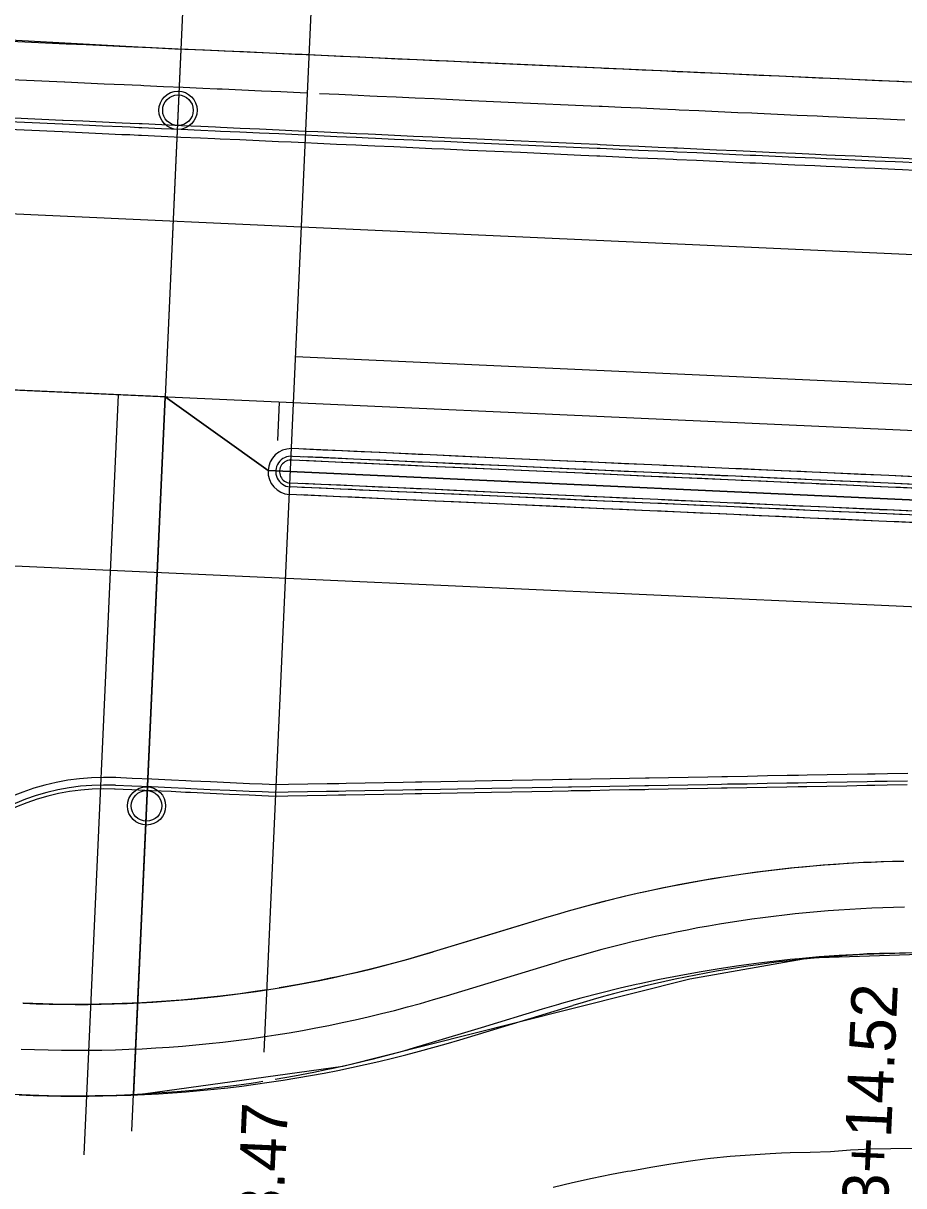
# Model space of a CAD drawing. Extents: x -70 to 701944, y -4 to 666871.
# Drawn here: x 665760.5 to 665875.7, y 656544.4 to 656696.4 of the extents above; entities that cross this region are included whole.
import ezdxf

# ---------------------------------------------------------------- set-up
doc = ezdxf.new("R2010")
doc.units = 0
for name, color, linetype in [('R_Detour', 7, 'Continuous'), ('R_Draft', 7, 'Continuous'), ('R_Horz Alg', 7, 'Continuous'), ('R_No Plot', 7, 'Continuous'), ('R_Proposed Const Limits', 7, 'Continuous'), ('R_Proposed Road', 7, 'Continuous'), ('R_Striping', 7, 'Continuous'), ('R_Water', 7, 'Continuous')]:
    doc.layers.add(name, color=color, linetype=linetype)

msp = doc.modelspace()

# ---------------------------------------------------------------- linework, layer by layer
at = {"layer": 'R_Detour'}
for p in [(665784.2, 656761.27), (665774.73, 656551.56)]:
    msp.add_line(p, (665779.07, 656647.56), dxfattribs=at)
at = {"layer": 'R_Draft'}
for p, q in [((665792.03, 656561.91), (665801.53, 656772.27)), ((665772.93, 656647.83), (665768.44, 656548.49))]:
    msp.add_line(p, q, dxfattribs=at)
at = {"layer": 'R_Horz Alg'}
msp.add_line((667725.26, 656559.62), (664961.47, 656684.5), dxfattribs=at)
msp.add_lwpolyline([(665793.82, 656641.88), (665794.05, 656646.88)], dxfattribs=at)
at = {"layer": 'R_No Plot'}
for p, q in [((667813.84, 656555.62), (664810.54, 656691.32)), ((667725.26, 656559.62), (664961.47, 656684.5)), ((665815.86, 656569.27), (665830.67, 656573.76))]:
    msp.add_line(p, q, dxfattribs=at)
for points in [[(665704.14, 656650.94), (665706.41, 656701.05), (665711.71, 656696.82), (665781.12, 656693.02), (665779.07, 656647.56)], [(665896, 656687.82), (665781.12, 656693.02), (665779.07, 656647.56), (665792.54, 656637.94), (665893.54, 656633.33)], [(665779.07, 656647.56), (665694.15, 656651.39), (665690.05, 656560.57), (665709.98, 656558.58), (665748.15, 656556.85), (665765.88, 656556.16), (665774.94, 656556.35)], [(665779.07, 656647.56), (665774.94, 656556.3), (665802.33, 656560.07), (665825, 656565.77), (665847.68, 656571.48), (665863.28, 656574.24), (665890.91, 656575.15), (665893.57, 656633.33), (665792.54, 656637.94)]]:
    msp.add_lwpolyline(points, close=True, dxfattribs=at)
for centre in [(665780.76, 656685.03), (665776.65, 656594.1)]:
    msp.add_circle(centre, 2.5, dxfattribs=at)
for centre, start, end in [((665878.78, 656414.88), 91.0369, 106.8465), ((665767.75, 656728.15), 267.4131, 286.8465)]:
    msp.add_arc(centre, 166, start, end, dxfattribs=at)
at = {"layer": 'R_Proposed Const Limits'}
msp.add_lwpolyline([(665879.73, 656549.3), (665873.97, 656549.29), (665871.34, 656549.21), (665869.72, 656549.13), (665868.7, 656549.08), (665866.07, 656548.9), (665863.44, 656548.81), (665860.82, 656548.74), (665859.69, 656548.7), (665858.21, 656548.62), (665855.59, 656548.46), (665852.99, 656548.26), (665850.38, 656547.99), (665849.64, 656547.9), (665847.79, 656547.65), (665845.2, 656547.26), (665842.61, 656546.83), (665840.04, 656546.37), (665839.56, 656546.29), (665837.47, 656545.9), (665834.92, 656545.38), (665832.37, 656544.82), (665829.84, 656544.21)], dxfattribs=at)
at = {"layer": 'R_Proposed Road'}
for p, q in [((665828.93, 656579.5), (665814.12, 656575.01)), ((665828.93, 656579.5), (665814.12, 656575.01)), ((665817.6, 656563.53), (665832.41, 656568.01))]:
    msp.add_line(p, q, dxfattribs=at)
for points in [[(665797.91, 656692.26), (665796.98, 656692.3), (665796.1, 656692.34), (665794.44, 656692.42), (665791.9, 656692.53), (665789.35, 656692.65), (665786.79, 656692.76), (665786.11, 656692.79), (665784.23, 656692.88), (665781.66, 656692.99), (665779.09, 656693.11), (665776.51, 656693.23), (665776.12, 656693.24), (665774.98, 656693.3), (665773.93, 656693.34), (665771.35, 656693.46), (665768.77, 656693.58), (665766.19, 656693.69), (665766.13, 656693.69), (665756.14, 656694.15)], [(665876.02, 656688.72), (665875.01, 656688.77), (665872.39, 656688.88), (665869.77, 656689), (665867.16, 656689.12), (665866.03, 656689.17), (665864.56, 656689.24), (665861.96, 656689.36), (665859.37, 656689.47), (665856.78, 656689.59), (665856.04, 656689.62), (665854.21, 656689.71), (665851.64, 656689.82), (665849.08, 656689.94), (665846.53, 656690.05), (665846.05, 656690.07), (665843.99, 656690.17), (665841.46, 656690.28), (665838.95, 656690.39), (665836.45, 656690.51), (665836.06, 656690.53), (665833.95, 656690.62), (665826.07, 656690.98), (665819.37, 656691.28), (665816.93, 656691.39), (665816.08, 656691.43), (665814.48, 656691.5), (665812.01, 656691.61), (665809.53, 656691.72), (665807.04, 656691.84), (665806.09, 656691.88), (665804.54, 656691.95), (665802.03, 656692.06), (665799.51, 656692.18), (665797.91, 656692.26)], [(665797.69, 656687.26), (665796.75, 656687.31), (665795.88, 656687.35), (665794.22, 656687.42), (665791.67, 656687.54), (665789.12, 656687.65), (665786.56, 656687.77), (665785.89, 656687.8), (665784, 656687.88), (665781.43, 656688), (665778.86, 656688.11), (665776.29, 656688.23), (665775.9, 656688.25), (665774.75, 656688.3), (665773.71, 656688.35), (665771.13, 656688.46), (665768.55, 656688.58), (665765.97, 656688.7), (665765.91, 656688.7), (665755.92, 656689.15)], [(665875.8, 656683.72), (665874.79, 656683.77), (665872.16, 656683.89), (665869.55, 656684.01), (665866.94, 656684.13), (665865.81, 656684.18), (665864.33, 656684.24), (665861.73, 656684.36), (665859.14, 656684.48), (665856.56, 656684.59), (665855.82, 656684.63), (665853.98, 656684.71), (665851.41, 656684.83), (665848.85, 656684.94), (665846.3, 656685.06), (665845.83, 656685.08), (665843.77, 656685.17), (665841.24, 656685.29), (665838.72, 656685.4), (665836.22, 656685.51), (665835.84, 656685.53), (665833.73, 656685.63), (665825.85, 656685.98), (665819.15, 656686.28), (665816.7, 656686.39), (665815.86, 656686.43), (665814.25, 656686.51), (665811.78, 656686.62), (665809.3, 656686.73), (665806.81, 656686.84), (665805.87, 656686.88), (665804.31, 656686.95), (665801.8, 656687.07), (665799.28, 656687.18)], [(665797.44, 656681.77), (665796.5, 656681.81), (665795.63, 656681.85), (665793.97, 656681.93), (665791.42, 656682.04), (665788.87, 656682.16), (665786.31, 656682.27), (665785.64, 656682.3), (665783.75, 656682.39), (665781.18, 656682.5), (665778.61, 656682.62), (665776.04, 656682.74), (665775.65, 656682.75), (665774.5, 656682.81), (665773.46, 656682.85), (665770.88, 656682.97), (665768.3, 656683.09), (665765.72, 656683.2), (665765.66, 656683.21), (665755.67, 656683.66)], [(665797.46, 656682.27), (665796.53, 656682.31), (665795.65, 656682.35), (665793.99, 656682.43), (665791.44, 656682.54), (665788.89, 656682.66), (665786.34, 656682.77), (665785.66, 656682.8), (665783.77, 656682.89), (665781.21, 656683), (665778.64, 656683.12), (665776.06, 656683.24), (665775.67, 656683.25), (665774.52, 656683.31), (665773.48, 656683.35), (665770.9, 656683.47), (665768.32, 656683.59), (665765.74, 656683.7), (665765.68, 656683.7), (665755.69, 656684.16)], [(665797.39, 656680.76), (665796.46, 656680.8), (665795.58, 656680.84), (665793.92, 656680.92), (665791.38, 656681.03), (665788.83, 656681.15), (665786.27, 656681.26), (665785.59, 656681.29), (665783.71, 656681.38), (665781.14, 656681.49), (665778.57, 656681.61), (665775.99, 656681.73), (665775.6, 656681.74), (665774.46, 656681.8), (665773.41, 656681.84), (665770.84, 656681.96), (665768.25, 656682.08), (665765.67, 656682.19), (665765.62, 656682.2), (665755.63, 656682.65)], [(665877.18, 656678.66), (665875.57, 656678.73), (665874.56, 656678.78), (665871.94, 656678.89), (665869.32, 656679.01), (665866.71, 656679.13), (665865.58, 656679.18), (665864.11, 656679.25), (665861.51, 656679.37), (665858.92, 656679.48), (665856.33, 656679.6), (665855.59, 656679.63), (665853.75, 656679.72), (665851.19, 656679.83), (665848.63, 656679.95), (665846.08, 656680.06), (665845.6, 656680.08), (665843.54, 656680.18), (665841.01, 656680.29), (665838.5, 656680.4), (665835.99, 656680.52), (665835.61, 656680.54), (665833.5, 656680.63), (665825.62, 656680.99), (665818.92, 656681.29), (665816.48, 656681.4), (665815.63, 656681.44), (665814.02, 656681.51), (665811.56, 656681.62), (665809.08, 656681.73), (665806.59, 656681.85), (665805.64, 656681.89), (665804.09, 656681.96), (665801.58, 656682.07), (665799.06, 656682.19), (665797.46, 656682.27)], [(665877.12, 656677.16), (665875.5, 656677.23), (665874.49, 656677.28), (665871.87, 656677.4), (665869.26, 656677.51), (665866.64, 656677.63), (665865.51, 656677.68), (665864.04, 656677.75), (665861.44, 656677.87), (665858.85, 656677.98), (665856.26, 656678.1), (665855.52, 656678.13), (665853.69, 656678.22), (665851.12, 656678.33), (665848.56, 656678.45), (665846.01, 656678.56), (665845.53, 656678.59), (665843.47, 656678.68), (665840.95, 656678.79), (665838.43, 656678.91), (665835.93, 656679.02), (665835.54, 656679.04), (665833.44, 656679.13), (665825.55, 656679.49), (665818.85, 656679.79), (665816.41, 656679.9), (665815.56, 656679.94), (665813.96, 656680.01), (665811.49, 656680.12), (665809.01, 656680.24), (665806.52, 656680.35), (665805.57, 656680.39), (665804.02, 656680.46), (665801.51, 656680.57), (665798.99, 656680.69), (665797.39, 656680.76)], [(665877.16, 656678.16), (665875.55, 656678.23), (665874.54, 656678.28), (665871.92, 656678.39), (665869.3, 656678.51), (665866.69, 656678.63), (665865.56, 656678.68), (665864.08, 656678.75), (665861.49, 656678.87), (665858.89, 656678.98), (665856.31, 656679.1), (665855.57, 656679.13), (665853.73, 656679.22), (665851.16, 656679.33), (665848.61, 656679.45), (665846.06, 656679.56), (665845.58, 656679.58), (665843.52, 656679.68), (665840.99, 656679.79), (665838.47, 656679.91), (665835.97, 656680.02), (665835.59, 656680.04), (665833.48, 656680.13), (665825.6, 656680.49), (665818.9, 656680.79), (665816.46, 656680.9), (665815.61, 656680.94), (665814, 656681.01), (665811.53, 656681.12), (665809.06, 656681.23), (665806.57, 656681.35), (665805.62, 656681.39), (665804.06, 656681.46), (665801.55, 656681.57), (665799.03, 656681.69), (665797.44, 656681.77)], [(665993.58, 656631.86), (665983.59, 656632.31), (665973.6, 656632.76), (665963.61, 656633.21), (665953.62, 656633.66), (665943.63, 656634.11), (665933.64, 656634.56), (665923.65, 656635.02), (665913.66, 656635.47), (665903.67, 656635.92), (665893.68, 656636.37), (665883.69, 656636.82), (665873.7, 656637.27), (665863.71, 656637.72), (665853.72, 656638.17), (665843.73, 656638.63), (665833.74, 656639.08), (665823.75, 656639.53), (665813.76, 656639.98), (665795.59, 656640.8)], [(665993.53, 656630.86), (665983.54, 656631.31), (665973.55, 656631.76), (665963.56, 656632.21), (665953.57, 656632.66), (665943.58, 656633.11), (665933.59, 656633.57), (665923.6, 656634.02), (665913.61, 656634.47), (665903.62, 656634.92), (665893.63, 656635.37), (665883.64, 656635.82), (665873.65, 656636.27), (665863.66, 656636.72), (665853.67, 656637.18), (665843.68, 656637.63), (665833.69, 656638.08), (665823.7, 656638.53), (665813.71, 656638.98), (665795.72, 656639.79)], [(665877.89, 656636.08), (665875.27, 656636.2), (665873.65, 656636.27), (665872.64, 656636.32), (665870.02, 656636.44), (665867.41, 656636.56), (665864.79, 656636.67), (665863.66, 656636.72), (665862.19, 656636.79), (665859.59, 656636.91), (665857, 656637.03), (665854.41, 656637.14), (665853.67, 656637.18), (665851.84, 656637.26), (665849.27, 656637.37), (665846.71, 656637.49), (665844.16, 656637.61), (665843.68, 656637.63), (665841.62, 656637.72), (665839.09, 656637.83), (665836.58, 656637.95), (665834.08, 656638.06), (665833.69, 656638.08), (665831.59, 656638.17), (665823.7, 656638.53), (665817, 656638.83), (665814.56, 656638.94), (665813.71, 656638.98), (665812.11, 656639.05), (665809.64, 656639.17), (665807.16, 656639.28), (665804.67, 656639.39), (665803.72, 656639.43), (665802.17, 656639.5), (665799.66, 656639.62), (665797.14, 656639.73)], [(665877.94, 656637.08), (665875.31, 656637.2), (665873.7, 656637.27), (665872.69, 656637.32), (665870.07, 656637.44), (665867.45, 656637.55), (665864.84, 656637.67), (665863.71, 656637.72), (665862.23, 656637.79), (665859.63, 656637.91), (665857.04, 656638.02), (665854.46, 656638.14), (665853.72, 656638.17), (665851.88, 656638.26), (665849.31, 656638.37), (665846.75, 656638.49), (665844.21, 656638.6), (665843.73, 656638.63), (665841.67, 656638.72), (665839.14, 656638.83), (665836.62, 656638.95), (665834.12, 656639.06), (665833.74, 656639.08), (665831.63, 656639.17), (665823.75, 656639.53), (665817.05, 656639.83), (665814.61, 656639.94), (665813.76, 656639.98), (665812.15, 656640.05), (665809.68, 656640.16), (665807.21, 656640.28), (665804.71, 656640.39), (665803.77, 656640.43), (665802.21, 656640.5), (665799.7, 656640.62), (665797.18, 656640.73)], [(665993.51, 656630.36), (665983.52, 656630.81), (665973.53, 656631.26), (665963.54, 656631.71), (665953.55, 656632.16), (665943.56, 656632.61), (665933.57, 656633.07), (665923.58, 656633.52), (665913.59, 656633.97), (665903.6, 656634.42), (665893.61, 656634.87), (665883.62, 656635.32), (665873.63, 656635.77), (665863.64, 656636.23), (665853.65, 656636.68), (665843.66, 656637.13), (665833.67, 656637.58), (665823.68, 656638.03), (665813.69, 656638.48), (665795.69, 656639.3)], [(665877.87, 656635.58), (665875.24, 656635.7), (665873.63, 656635.77), (665872.62, 656635.82), (665870, 656635.94), (665867.38, 656636.06), (665864.77, 656636.17), (665863.64, 656636.23), (665862.17, 656636.29), (665859.57, 656636.41), (665856.97, 656636.53), (665854.39, 656636.64), (665853.65, 656636.68), (665851.81, 656636.76), (665849.25, 656636.88), (665846.69, 656636.99), (665844.14, 656637.11), (665843.66, 656637.13), (665841.6, 656637.22), (665839.07, 656637.34), (665836.56, 656637.45), (665834.05, 656637.56), (665833.67, 656637.58), (665831.56, 656637.67), (665823.68, 656638.03), (665816.98, 656638.33), (665814.54, 656638.44), (665813.69, 656638.48), (665812.08, 656638.55), (665809.62, 656638.67), (665807.14, 656638.78), (665804.65, 656638.89), (665803.7, 656638.93), (665802.15, 656639), (665799.63, 656639.12), (665797.11, 656639.23)], [(665993.35, 656626.86), (665983.36, 656627.31), (665973.37, 656627.76), (665963.38, 656628.22), (665953.39, 656628.67), (665943.4, 656629.12), (665933.41, 656629.57), (665923.42, 656630.02), (665913.43, 656630.47), (665903.44, 656630.92), (665893.45, 656631.37), (665883.46, 656631.83), (665873.47, 656632.28), (665863.48, 656632.73), (665853.49, 656633.18), (665843.5, 656633.63), (665833.51, 656634.08), (665823.52, 656634.53), (665813.53, 656634.99), (665795.39, 656635.81)], [(665993.37, 656627.36), (665983.38, 656627.81), (665973.39, 656628.26), (665963.4, 656628.71), (665953.41, 656629.17), (665943.42, 656629.62), (665933.43, 656630.07), (665923.44, 656630.52), (665913.45, 656630.97), (665903.46, 656631.42), (665893.47, 656631.87), (665883.48, 656632.33), (665873.49, 656632.78), (665863.5, 656633.23), (665853.51, 656633.68), (665843.53, 656634.13), (665833.54, 656634.58), (665823.55, 656635.03), (665813.56, 656635.48), (665795.43, 656636.3)], [(665877.71, 656632.09), (665875.09, 656632.2), (665873.47, 656632.28), (665872.46, 656632.32), (665869.84, 656632.44), (665867.22, 656632.56), (665864.61, 656632.68), (665863.48, 656632.73), (665862.01, 656632.8), (665859.41, 656632.91), (665856.82, 656633.03), (665854.23, 656633.15), (665853.49, 656633.18), (665851.66, 656633.26), (665849.09, 656633.38), (665846.53, 656633.49), (665843.98, 656633.61), (665843.5, 656633.63), (665841.44, 656633.72), (665838.91, 656633.84), (665836.4, 656633.95), (665833.9, 656634.07), (665833.51, 656634.08), (665831.4, 656634.18), (665823.52, 656634.53), (665816.82, 656634.84), (665814.38, 656634.95), (665813.53, 656634.99), (665811.93, 656635.06), (665809.46, 656635.17), (665806.98, 656635.28), (665804.49, 656635.39), (665803.54, 656635.44), (665801.99, 656635.51), (665799.48, 656635.62), (665796.96, 656635.73)], [(665877.73, 656632.59), (665875.11, 656632.7), (665873.49, 656632.78), (665872.48, 656632.82), (665869.86, 656632.94), (665867.25, 656633.06), (665864.64, 656633.18), (665863.5, 656633.23), (665862.03, 656633.29), (665859.43, 656633.41), (665856.84, 656633.53), (665854.25, 656633.65), (665853.51, 656633.68), (665851.68, 656633.76), (665849.11, 656633.88), (665846.55, 656633.99), (665844, 656634.11), (665843.53, 656634.13), (665841.46, 656634.22), (665838.94, 656634.34), (665836.42, 656634.45), (665833.92, 656634.56), (665833.54, 656634.58), (665831.43, 656634.68), (665823.55, 656635.03), (665816.84, 656635.34), (665814.4, 656635.45), (665813.56, 656635.48), (665811.95, 656635.56), (665809.48, 656635.67), (665807, 656635.78), (665804.51, 656635.89), (665803.57, 656635.94), (665802.01, 656636.01), (665799.5, 656636.12), (665796.98, 656636.23)], [(665993.3, 656625.86), (665983.31, 656626.31), (665973.32, 656626.76), (665963.34, 656627.22), (665953.35, 656627.67), (665943.36, 656628.12), (665933.37, 656628.57), (665923.38, 656629.02), (665913.39, 656629.47), (665903.4, 656629.92), (665893.41, 656630.38), (665883.42, 656630.83), (665873.43, 656631.28), (665863.44, 656631.73), (665853.45, 656632.18), (665843.46, 656632.63), (665833.47, 656633.08), (665823.48, 656633.54), (665813.49, 656633.99), (665795.32, 656634.81)], [(665877.67, 656631.09), (665875.04, 656631.21), (665873.43, 656631.28), (665872.42, 656631.32), (665869.8, 656631.44), (665867.18, 656631.56), (665864.57, 656631.68), (665863.44, 656631.73), (665861.96, 656631.8), (665859.36, 656631.91), (665856.77, 656632.03), (665854.19, 656632.15), (665853.45, 656632.18), (665851.61, 656632.26), (665849.04, 656632.38), (665846.48, 656632.5), (665843.93, 656632.61), (665843.46, 656632.63), (665841.4, 656632.73), (665838.87, 656632.84), (665836.35, 656632.95), (665833.85, 656633.07), (665833.47, 656633.08), (665831.36, 656633.18), (665823.48, 656633.54), (665816.78, 656633.84), (665814.34, 656633.95), (665813.49, 656633.99), (665811.88, 656634.06), (665809.41, 656634.17), (665806.93, 656634.28), (665804.44, 656634.4), (665803.5, 656634.44), (665801.94, 656634.51), (665799.43, 656634.62), (665796.91, 656634.74)], [(665793.6, 656596.85), (665792.67, 656596.89), (665791.79, 656596.93), (665790.13, 656597), (665787.59, 656597.12), (665785.03, 656597.23), (665782.48, 656597.35), (665781.8, 656597.38), (665779.91, 656597.46), (665777.35, 656597.58), (665774.78, 656597.7), (665772.56, 656597.8)], [(665876.14, 656597.34), (665873.51, 656597.29), (665871.89, 656597.27), (665870.88, 656597.25), (665868.25, 656597.2), (665865.62, 656597.15), (665863.01, 656597.1), (665861.87, 656597.08), (665860.39, 656597.06), (665857.79, 656597.01), (665855.19, 656596.96), (665852.6, 656596.92), (665851.85, 656596.9), (665850.01, 656596.87), (665847.44, 656596.82), (665844.87, 656596.78), (665842.31, 656596.73), (665841.83, 656596.72), (665839.77, 656596.68), (665837.23, 656596.64), (665834.71, 656596.59), (665832.2, 656596.55), (665831.82, 656596.54), (665829.7, 656596.5), (665821.8, 656596.36), (665815.08, 656596.24), (665812.63, 656596.19), (665811.78, 656596.18), (665810.17, 656596.15), (665807.69, 656596.1), (665805.21, 656596.06), (665802.71, 656596.01), (665801.76, 656596), (665800.2, 656595.97), (665797.68, 656595.92), (665795.16, 656595.88), (665793.56, 656595.84)], [(665876.19, 656598.34), (665873.55, 656598.29), (665871.94, 656598.26), (665870.92, 656598.25), (665868.29, 656598.2), (665865.67, 656598.15), (665863.05, 656598.1), (665861.92, 656598.08), (665860.44, 656598.06), (665857.83, 656598.01), (665855.23, 656597.96), (665852.64, 656597.91), (665851.9, 656597.9), (665850.06, 656597.87), (665847.48, 656597.82), (665844.91, 656597.77), (665842.36, 656597.73), (665841.88, 656597.72), (665839.81, 656597.68), (665837.28, 656597.64), (665834.76, 656597.59), (665832.25, 656597.55), (665831.86, 656597.54), (665829.75, 656597.5), (665821.84, 656597.36), (665815.12, 656597.24), (665812.67, 656597.19), (665811.82, 656597.18), (665810.21, 656597.15), (665807.74, 656597.1), (665805.25, 656597.06), (665802.75, 656597.01), (665801.81, 656596.99), (665800.25, 656596.97), (665797.73, 656596.92), (665795.2, 656596.88), (665793.6, 656596.85)], [(665793.53, 656595.34), (665792.6, 656595.38), (665791.73, 656595.42), (665790.06, 656595.49), (665787.52, 656595.61), (665784.97, 656595.72), (665782.41, 656595.84), (665781.74, 656595.87), (665779.85, 656595.96), (665777.28, 656596.07), (665774.71, 656596.19), (665772.47, 656596.29)], [(665793.56, 656595.84), (665792.62, 656595.88), (665791.75, 656595.92), (665790.08, 656595.99), (665787.54, 656596.11), (665784.99, 656596.22), (665782.43, 656596.34), (665781.76, 656596.37), (665779.87, 656596.46), (665777.3, 656596.57), (665774.73, 656596.69), (665772.58, 656596.78)], [(665876.12, 656596.84), (665873.49, 656596.79), (665871.87, 656596.77), (665870.85, 656596.75), (665868.23, 656596.7), (665865.6, 656596.65), (665862.98, 656596.6), (665861.85, 656596.58), (665860.37, 656596.56), (665857.76, 656596.51), (665855.16, 656596.46), (665852.57, 656596.42), (665851.83, 656596.4), (665849.99, 656596.37), (665847.41, 656596.32), (665844.85, 656596.28), (665842.29, 656596.23), (665841.81, 656596.22), (665839.75, 656596.18), (665837.21, 656596.14), (665834.69, 656596.09), (665832.18, 656596.05), (665831.79, 656596.04), (665829.68, 656596), (665821.78, 656595.86), (665815.06, 656595.74), (665812.61, 656595.69), (665811.76, 656595.68), (665810.15, 656595.65), (665807.67, 656595.6), (665805.18, 656595.56), (665802.69, 656595.51), (665801.74, 656595.5), (665800.18, 656595.47), (665797.66, 656595.42), (665795.13, 656595.38), (665793.53, 656595.34)], [(665875.67, 656586.85), (665873.03, 656586.78), (665871.41, 656586.72), (665870.4, 656586.68), (665867.77, 656586.53), (665865.14, 656586.34), (665862.51, 656586.11), (665861.37, 656586), (665859.89, 656585.84), (665857.27, 656585.53), (665854.66, 656585.18), (665852.05, 656584.79), (665851.3, 656584.67), (665849.45, 656584.36), (665846.85, 656583.89), (665844.26, 656583.38), (665841.69, 656582.83), (665841.2, 656582.73), (665839.12, 656582.24), (665836.55, 656581.62), (665834, 656580.95), (665831.46, 656580.24), (665831.08, 656580.13), (665828.93, 656579.5), (665820.93, 656577.07), (665814.12, 656575.01), (665811.64, 656574.28), (665810.78, 656574.04), (665809.15, 656573.6), (665806.65, 656572.95), (665804.14, 656572.34), (665801.61, 656571.77), (665800.66, 656571.57), (665799.08, 656571.25), (665796.55, 656570.76), (665794, 656570.32)], [(665880.89, 656574.97), (665875.13, 656574.86), (665872.49, 656574.8), (665870.87, 656574.74), (665869.86, 656574.69), (665867.22, 656574.54), (665864.59, 656574.35), (665861.97, 656574.12), (665860.83, 656574.01), (665859.35, 656573.85), (665856.73, 656573.54), (665854.11, 656573.19), (665851.51, 656572.8), (665850.76, 656572.68), (665848.9, 656572.37), (665846.31, 656571.9), (665843.72, 656571.39), (665841.14, 656570.85), (665840.66, 656570.74), (665838.57, 656570.26), (665836.01, 656569.63), (665833.46, 656568.96), (665830.92, 656568.26), (665830.53, 656568.14), (665828.39, 656567.51), (665820.39, 656565.09), (665813.58, 656563.03), (665811.1, 656562.3), (665810.24, 656562.05), (665808.61, 656561.61), (665806.11, 656560.96), (665803.59, 656560.35), (665801.07, 656559.78), (665800.12, 656559.58), (665798.54, 656559.26), (665796, 656558.77), (665793.46, 656558.33)], [(665792.39, 656570.06), (665791.45, 656569.91), (665790.57, 656569.78), (665788.89, 656569.55), (665786.33, 656569.23), (665783.76, 656568.95), (665781.18, 656568.71), (665780.51, 656568.66), (665778.61, 656568.52), (665776.03, 656568.36), (665773.45, 656568.25), (665770.86, 656568.18), (665770.47, 656568.17), (665769.32, 656568.15), (665768.28, 656568.15), (665765.69, 656568.16), (665763.11, 656568.21), (665760.53, 656568.31), (665760.47, 656568.31)], [(665791.85, 656558.07), (665790.91, 656557.92), (665790.03, 656557.79), (665788.35, 656557.56), (665785.78, 656557.24), (665783.21, 656556.96), (665780.64, 656556.72), (665779.96, 656556.67), (665778.06, 656556.53), (665775.49, 656556.37), (665772.9, 656556.26), (665770.32, 656556.19), (665769.93, 656556.18), (665768.78, 656556.17), (665767.74, 656556.16), (665765.15, 656556.17), (665762.57, 656556.23), (665759.99, 656556.32)]]:
    msp.add_lwpolyline(points, dxfattribs=at)
for centre, radius, start, end in [((665795.54, 656637.8), 3, 88.9455, 265.8805), ((665795.54, 656637.8), 2, 84.6427, 265.8805), ((665795.54, 656637.8), 1.5, 84.2143, 265.8805), ((665771.23, 656566.83), 31, 87.4131, 177.413), ((665771.23, 656566.83), 30, 87.4131, 177.413), ((665771.23, 656566.83), 29.5, 87.4131, 177.413), ((665878.78, 656414.88), 172, 91.0369, 106.8465), ((665878.78, 656414.88), 172, 91.0369, 106.8465), ((665767.75, 656728.15), 160, 267.4131, 286.8465), ((665767.75, 656728.15), 160, 267.4131, 286.8465), ((665878.78, 656414.88), 160, 91.0369, 106.8465), ((665767.75, 656728.15), 172, 267.4131, 286.8465)]:
    msp.add_arc(centre, radius, start, end, dxfattribs=at)
at = {"layer": 'R_Striping'}
for points in [[(665796.89, 656669.77), (665705.17, 656673.92), (665703.61, 656673.99)], [(666699.66, 656625.98), (666096.29, 656653.24), (665996.53, 656660.75), (665796.9, 656669.77)], [(665995.03, 656643.8), (665796.13, 656652.79)], [(666697.69, 656586.03), (666094.81, 656613.27), (665994.78, 656614.78), (665744.97, 656626.07)]]:
    msp.add_lwpolyline(points, dxfattribs=at)
at = {"layer": 'R_Water'}
for centre in [(665780.76, 656685.03), (665776.65, 656594.1)]:
    msp.add_circle(centre, 2, dxfattribs=at)

# ---------------------------------------------------------------- texts
at = {"layer": 'R_No Plot'}
for s, p in [('223+14.52 ', (665873.18, 656532.59)), ('223+93.47 ', (665793.44, 656517.01))]:
    msp.add_text(s, height=6, rotation=87.4131, dxfattribs=at).set_placement(p)

doc.saveas('drawing.dxf')
